// Mitsubishi GX Works2 project: 53.用编码器测量电机转速   PLC: FX3U/FX3UC

PROGRAM MAIN
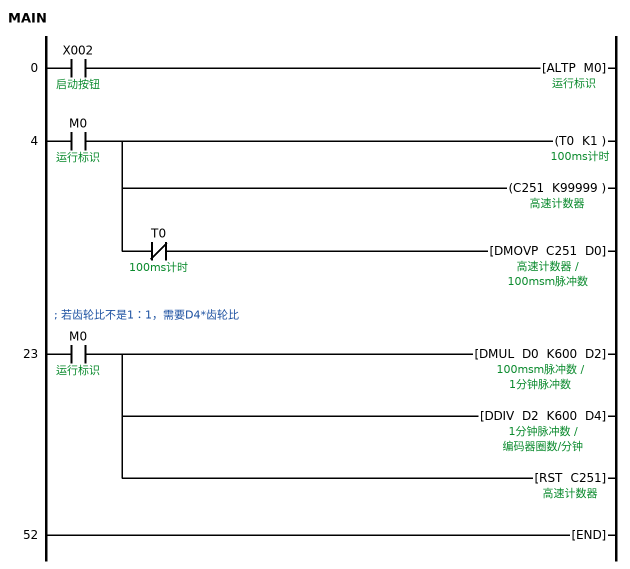
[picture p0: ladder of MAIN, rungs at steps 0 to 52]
0     LD      X002  ; 启动按钮
      ALTP    M0  ; 运行标识
4     LD      M0  ; 运行标识
      OUT     T0 K1  ; 100ms计时
      OUT     C251 K99999  ; 高速计数器
      ANI     T0  ; 100ms计时
      DMOVP   C251 D0  ; 100msm脉冲数
        [note] 采集100ms脉冲数
; 若齿轮比不是1：1，需要D4*齿轮比
23    LD      M0  ; 运行标识
      DMUL    D0 K600 D2  ; 1分钟脉冲数
        [note] D0*k600=1分钟脉冲数
      DDIV    D2 K600 D4  ; 编码器圈数/分钟
        [note] D2÷编码器分辨率（600）
      RST     C251  ; 高速计数器
        [note] 计算完成重置高速计数器
52    END
END_PROGRAM

// device comments not shown above
X000  ; 脉冲输入点
